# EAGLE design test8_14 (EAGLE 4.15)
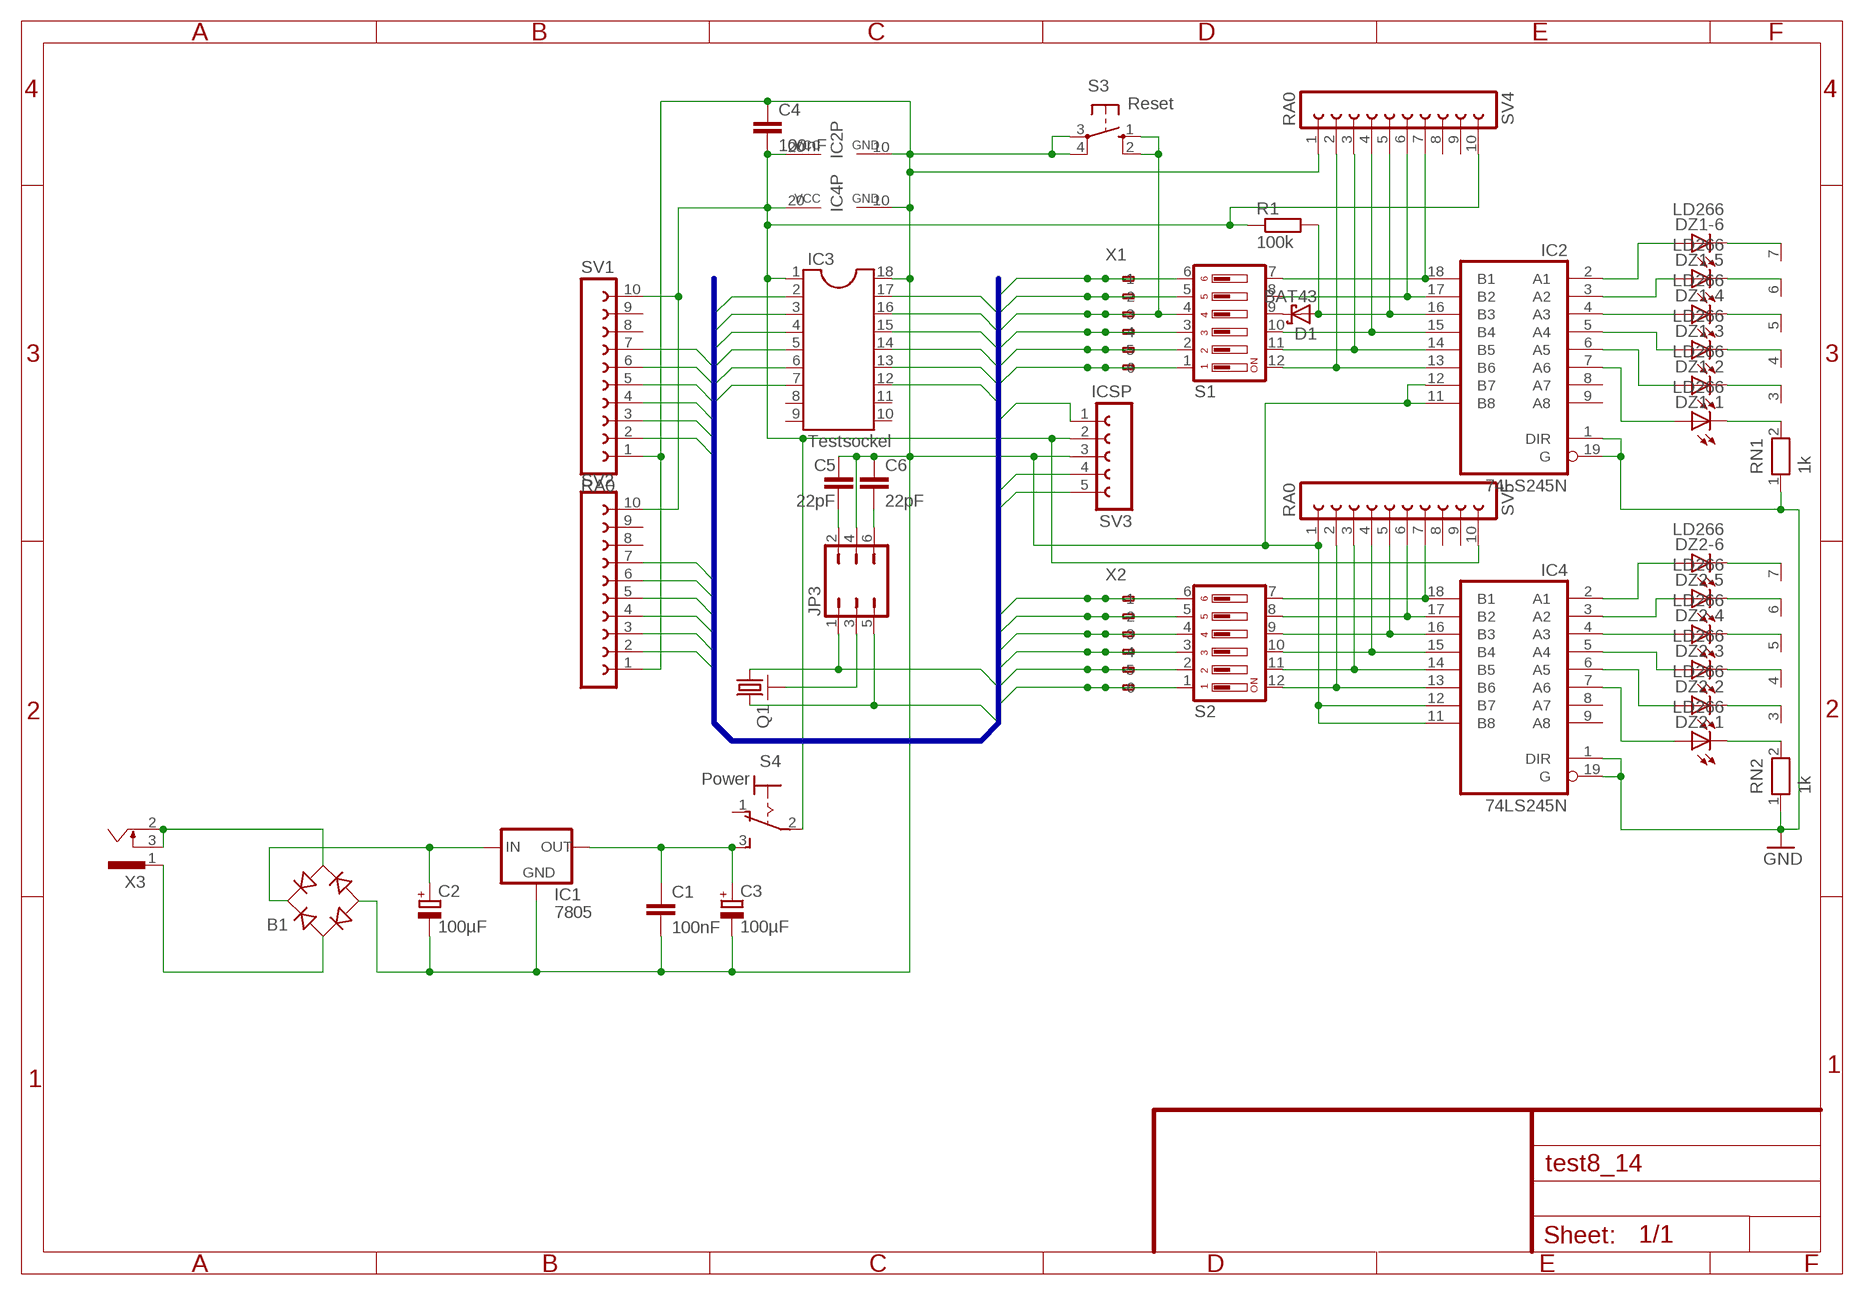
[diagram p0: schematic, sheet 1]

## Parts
B1  RB1A  [RB1A]
C1  100nF  C-EU050-025X075  [C050-025X075]
C2  100µF  CPOL-EUE2.5-7  [E2,5-7]
C3  100µF  CPOL-EUE2.5-7  [E2,5-7]
C4  100nF  C-EU050-025X075  [C050-025X075]
C5  22pF  C-EU025-025X050  [C025-025X050]
C6  22pF  C-EU025-025X050  [C025-025X050]
D1  BAT43  [DO35-10]
DZ1  LD266  [LD266]
DZ2  LD266  [LD266]
IC1  7805  78XXS  [78XXS]
IC2  74LS245N  [DIL20]
IC3  Testsockel  TEXTOOL18  [TEXTOOL18]
IC4  74LS245N  [DIL20]
JP3  JP3Q  [JP3Q]
Q1  RESONATOR  [RES3PIN]
R1  100k  R-EU_0207/12  [0207/12]
RN1  1k  RN06  [RN-7]
RN2  1k  RN06  [RN-7]
S1  DIP06YL  [DIP06YL]
S2  DIP06YL  [DIP06YL]
S3  Reset  10-XX  [B3F-10XX]
S4  Power  320-916  [320-916]
SV1  RA0  FE10-1  [FE10]
SV2  FE10-1  [FE10]
SV3  ICSP  FE05-1  [FE05-1]
SV4  RA0  FE10-1  [FE10]
SV5  RA0  FE10-1  [FE10]
X1  233-506  [233-506]
X2  233-506  [233-506]
X3  733989-55  [733989-5]

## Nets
GND: B1.- C1.2 C2.- C3.- C4.1 C5.1 C6.1 IC1.GND IC2.1(DIR) IC2.10(GND) IC2.11(B8) IC2.12(B7) IC2.19(G) IC3.18 IC4.1(DIR) IC4.10(GND) IC4.11(B8) IC4.12(B7) IC4.19(G) JP3.4 RN1.1 RN2.1 S3.3(P) S3.4(P1) SV1.1 SV2.1 SV3.3 SV4.1 SV5.1
N$1: DZ1.A2(-2:A) IC2.6(A5)
N$2: DZ1.A3(-3:A) IC2.5(A4)
N$3: DZ1.A4(-4:A) IC2.4(A3)
N$4: DZ1.A5(-5:A) IC2.3(A2)
N$5: DZ1.A1(-1:A) IC2.7(A6)
N$6: DZ1.A6(-6:A) IC2.2(A1)
N$7: DZ1.K6(-6:C) RN1.7
N$8: DZ1.K5(-5:C) RN1.6
N$9: DZ1.K4(-4:C) RN1.5
N$10: DZ1.K3(-3:C) RN1.4
N$11: DZ1.K2(-2:C) RN1.3
N$12: DZ1.K1(-1:C) RN1.2
N$13: DZ2.A4(-4:A) IC4.4(A3)
N$14: DZ2.A5(-5:A) IC4.3(A2)
N$15: DZ2.A6(-6:A) IC4.2(A1)
N$16: DZ2.A3(-3:A) IC4.5(A4)
N$17: DZ2.A2(-2:A) IC4.6(A5)
N$18: DZ2.A1(-1:A) IC4.7(A6)
N$19: DZ2.K6(-6:C) RN2.7
N$20: DZ2.K5(-5:C) RN2.6
N$21: DZ2.K4(-4:C) RN2.5
N$22: DZ2.K3(-3:C) RN2.4
N$23: DZ2.K2(-2:C) RN2.3
N$24: DZ2.K1(-1:C) RN2.2
N$25: IC2.18(B1) S1.7 SV4.7
N$26: IC2.17(B2) S1.8 SV4.6
N$27: D1.C S1.9
N$28: IC2.15(B4) S1.10 SV4.4
N$29: IC2.14(B5) S1.11 SV4.3
N$30: IC2.13(B6) S1.12 SV4.2
N$31: IC4.18(B1) S2.7 SV5.7
N$32: IC4.17(B2) S2.8 SV5.6
N$33: IC4.16(B3) S2.9 SV5.5
N$34: IC4.15(B4) S2.10 SV5.4
N$35: IC4.14(B5) S2.11 SV5.3
N$36: IC4.13(B6) S2.12 SV5.2
N$37: D1.A IC2.16(B3) R1.2 SV4.5
N$38: C5.2 JP3.2
N$39: C6.2 JP3.6
N$40: JP3.3 Q1.2
N$45: B1.+ C2.+ IC1.IN
N$48: B1.AC2 X3.2 X3.3
N$49: B1.AC1 X3.1
N$50: C1.1 C3.+ IC1.OUT S4.3(S)
RA0: IC3.17 S1.1 SV1.2 SV3.4 X1.A6(-6) X1.B6(B-6)
RA1: IC3.16 S1.2 SV1.3 SV3.5 X1.A5(-5) X1.B5(B-5)
RA2: IC3.15 S1.3 SV1.4 X1.A4(-4) X1.B4(B-4)
RA3: IC3.4 S1.4 S3.1(S) S3.2(S1) SV1.5 SV3.1 X1.A3(-3) X1.B3(B-3)
RA4: IC3.3 JP3.5 Q1.3 S1.5 SV1.6 X1.A2(-2) X1.B2(B-2)
RA5: IC3.2 JP3.1 Q1.1 S1.6 SV1.7 X1.A1(-1) X1.B1(B-1)
RC0: IC3.14 S2.1 SV2.2 X2.A6(-6) X2.B6(B-6)
RC1: IC3.13 S2.2 SV2.3 X2.A5(-5) X2.B5(B-5)
RC2: IC3.12 S2.3 SV2.4 X2.A4(-4) X2.B4(B-4)
RC3: IC3.7 S2.4 SV2.5 X2.A3(-3) X2.B3(B-3)
RC4: IC3.6 S2.5 SV2.6 X2.A2(-2) X2.B2(B-2)
RC5: IC3.5 S2.6 SV2.7 X2.A1(-1) X2.B1(B-1)
VSS: C4.2 IC2.20(VCC) IC3.1 IC4.20(VCC) R1.1 S4.2(P) SV1.10 SV2.10 SV3.2 SV4.10 SV5.10
Unconnected: IC2.8(A7) IC2.9(A8) IC3.8 IC3.9 IC3.10 IC3.11 IC4.8(A7) IC4.9(A8) S4.1(O) SV1.8 SV1.9 SV2.8 SV2.9 SV4.8 SV4.9 SV5.8 SV5.9

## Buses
RA[0..5],RC[0..5]

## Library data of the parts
B1 = rectifier:RB1A: RECTIFIER 1 A
C1 C4-C6 = rcl:C-EU: CAPACITOR, European symbol
C2 C3 = rcl:CPOL-EU: POLARIZED CAPACITOR, European symbol
D1 = sprut:BAT43: DIODE
DZ1 DZ2 = led:LD266: LED BLOCK 6 LEDs, Siemens
IC1 = v-reg:78XXS: VOLTAGE REGULATOR
IC2 IC4 = 74xx-eu:74*245: Octal BUS TRANSCEIVER, 3-state
IC3 = sprut:TEXTOOL18: Dual In Line
JP3 = jumper:JP3Q: JUMPER
Q1 = sprut:RESONATOR: CRYSTAL
R1 = rcl:R-EU_: RESISTOR, European symbol
RN1 RN2 = resistor-net:RN06: RESISTOR NETWORK
S1 S2 = switch-dil:DIP06YL: DIL/CODE SWITCH
S3 = switch-omron:10-XX: OMRON SWITCH
S4 = switch:320-916: TOGGLE SWITCH distributor RS Components
SV1 SV2 SV4 SV5 = con-lsta:FE10-1: FEMALE HEADER
SV3 = con-lsta:FE05-1: FEMALE HEADER
X1 X2 = con-wago:233-506: WAGO Cage Clamp
X3 = con-conrad:733989-55: FEMALE PRINT CONNECTOR 1.1 mm, FUK HING Industries, distributor Conrad

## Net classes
1 VCC: width 5.08 mm
2 GND: width 5.08 mm

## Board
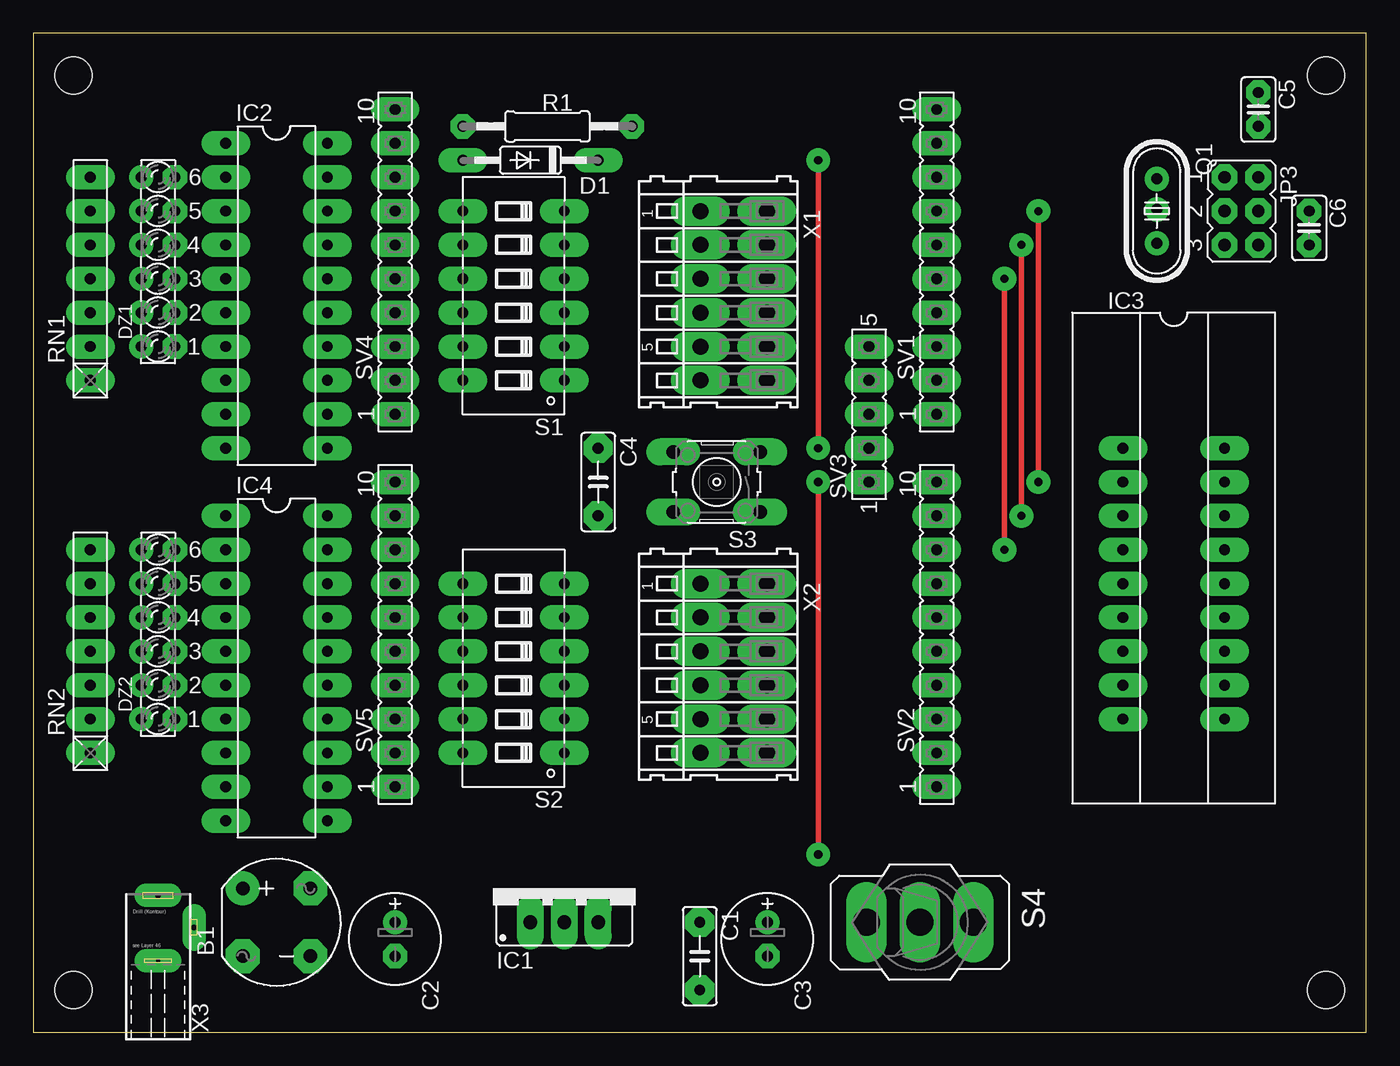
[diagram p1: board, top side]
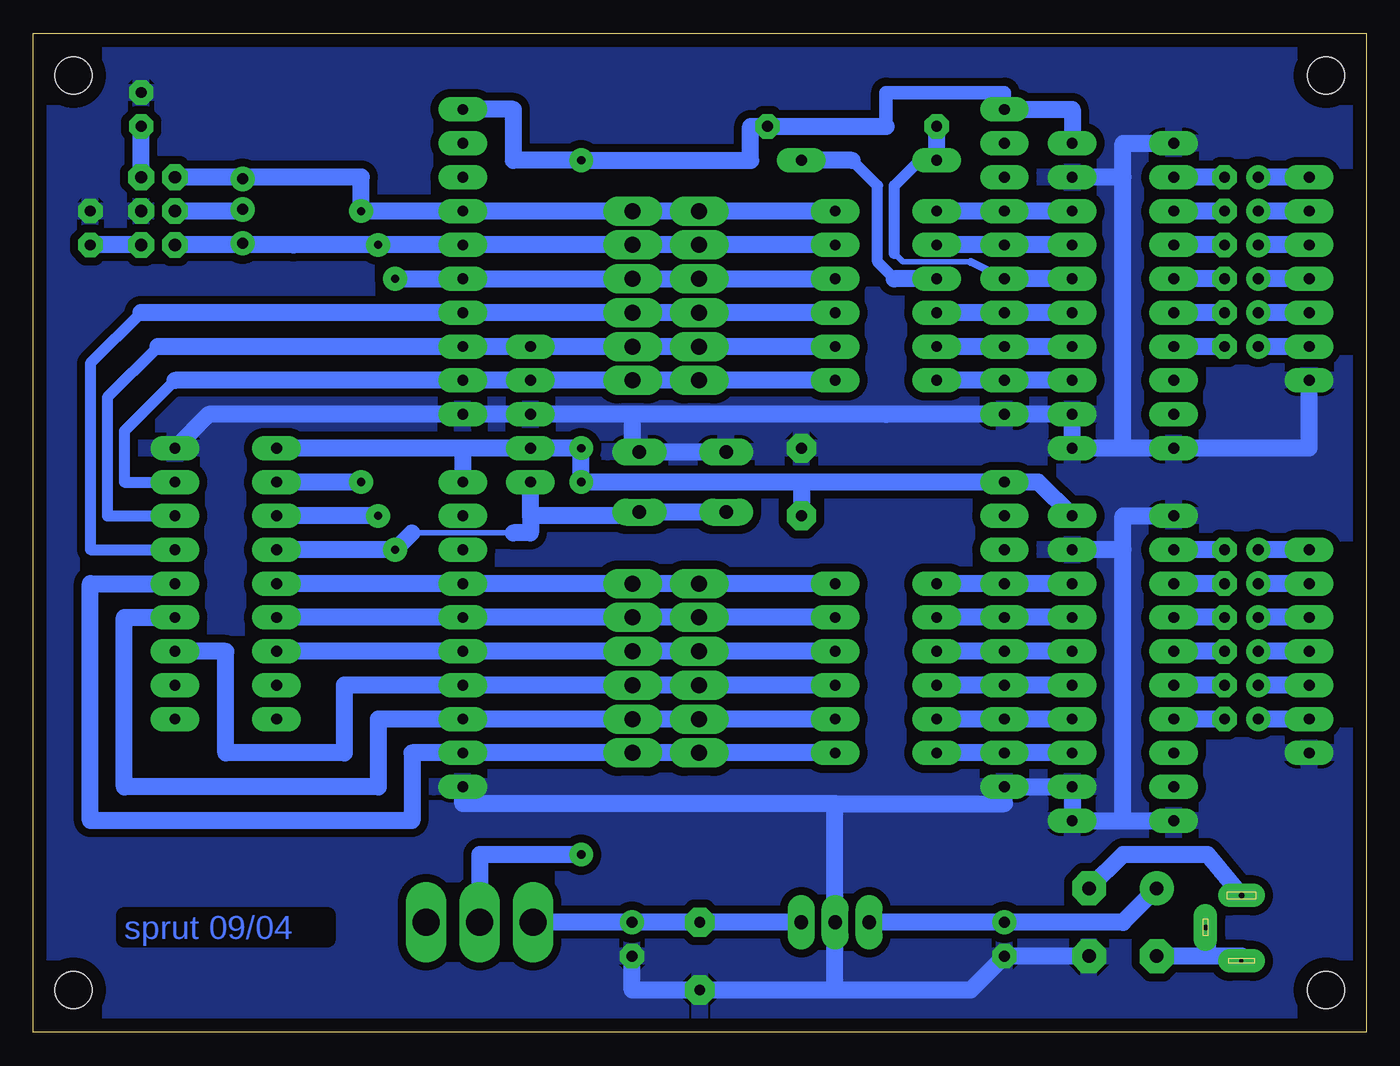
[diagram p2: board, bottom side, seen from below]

Size 100 x 74.92 mm. Coordinates in mm from the lower left corner, seen from the top.
Outline: 0,0 100,0 100,74.92 0,74.92 0,0
Copper layers (1*16): Top 0.035mm / dielectric 1.5mm / Bottom 0.035mm
Design rules "leiterplatte mit löchern": minimum track width 10mil, minimum drill 12mil, track to track 8mil, track to pad 8mil, pad to pad 8mil, via to via 8mil, smd to smd 8mil, copper to edge 40mil, drill to drill 8mil, minimum pad ring 20mil, minimum via ring 8mil, stop-mask expansion 4mil, vias tented up to drill 0mil, thermal gap 10mil
Holes 2.8 mm at 3.01,71.75 96.99,71.75 96.99,3.17 3.01,3.17

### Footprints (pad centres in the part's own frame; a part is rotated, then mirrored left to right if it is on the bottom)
RB1A = drill 1.016 pad 2.54 round: + -2.54,2.54 | drill 1.016 pad 2.54 octagon: - 2.54,-2.54; AC1 2.54,2.54; AC2 -2.54,-2.54
C050-025X075 = drill 0.813 pad 2.184 octagon: 1 -2.54,0; 2 2.54,0
E2,5-7 = drill 0.813 pad 1.6 round: + -1.27,0 | drill 0.813 pad 1.6 octagon: - 1.27,0
C025-025X050 = drill 0.813 pad 1.778 octagon: 1 -1.27,0; 2 1.27,0
DO35-10 = drill 0.813 long: A 5.08,0; C -5.08,0
LD266 = drill 0.813 octagon: A1 -1.27,6.35; A2 -1.27,3.81; A3 -1.27,1.27; A4 -1.27,-1.27; A5 -1.27,-3.81; A6 -1.27,-6.35 | drill 0.813 round: K1 1.27,6.35; K2 1.27,3.81; K3 1.27,1.27; K4 1.27,-1.27; K5 1.27,-3.81; K6 1.27,-6.35
78XXS = drill 1.016 long: GND 0,-2.54; IN -2.54,-2.54; OUT 2.54,-2.54
DIL20 = drill 0.813 long: 1 -11.43,-3.81; 2 -8.89,-3.81; 3 -6.35,-3.81; 4 -3.81,-3.81; 5 -1.27,-3.81; 6 1.27,-3.81; 7 3.81,-3.81; 8 6.35,-3.81; 9 8.89,-3.81; 10 11.43,-3.81; 11 11.43,3.81; 12 8.89,3.81; 13 6.35,3.81; 14 3.81,3.81; 15 1.27,3.81; 16 -1.27,3.81; 17 -3.81,3.81; 18 -6.35,3.81; 19 -8.89,3.81; 20 -11.43,3.81
TEXTOOL18 = drill 0.813 long: 1 -10.16,-3.81; 2 -7.62,-3.81; 3 -5.08,-3.81; 4 -2.54,-3.81; 5 0,-3.81; 6 2.54,-3.81; 7 5.08,-3.81; 8 7.62,-3.81; 9 10.16,-3.81; 10 10.16,3.81; 11 7.62,3.81; 12 5.08,3.81; 13 2.54,3.81; 14 0,3.81; 15 -2.54,3.81; 16 -5.08,3.81; 17 -7.62,3.81; 18 -10.16,3.81
JP3Q = drill 0.914 octagon: 1 -2.54,-1.27; 2 -2.54,1.27; 3 0,-1.27; 4 0,1.27; 5 2.54,-1.27; 6 2.54,1.27
RES3PIN = drill 0.813 round: 1 -2.413,0; 2 -0.127,0; 3 2.413,0
0207/12 = drill 0.813 octagon: 1 -6.35,0; 2 6.35,0
RN-7 = drill 0.813 long: 1 -7.62,0; 2 -5.08,0; 3 -2.54,0; 4 0,0; 5 2.54,0; 6 5.08,0; 7 7.62,0
DIP06YL = drill 0.813 long: 1 -6.35,-3.81; 2 -3.81,-3.81; 3 -1.27,-3.81; 4 1.27,-3.81; 5 3.81,-3.81; 6 6.35,-3.81; 7 6.35,3.81; 8 3.81,3.81; 9 1.27,3.81; 10 -1.27,3.81; 11 -3.81,3.81; 12 -6.35,3.81
B3F-10XX = drill 1.016 long: 1 -3.251,2.261; 2 3.251,2.261; 3 -3.251,-2.261; 4 3.251,-2.261
320-916 = drill 2.007 long: 1 0,4.013; 2 0,0; 3 0,-4.013
FE10 = drill 0.813 long: 1 -11.43,0; 2 -8.89,0; 3 -6.35,0; 4 -3.81,0; 5 -1.27,0; 6 1.27,0; 7 3.81,0; 8 6.35,0; 9 8.89,0; 10 11.43,0
FE05-1 = drill 0.813 long: 1 -5.08,0; 2 -2.54,0; 3 0,0; 4 2.54,0; 5 5.08,0
233-506 = drill 1.2 long: A1 -6.35,2.5; A2 -3.81,2.5; A3 -1.27,2.5; A4 1.27,2.5; A5 3.81,2.5; A6 6.35,2.5; B1 -6.35,-2.5; B2 -3.81,-2.5; B3 -1.27,-2.5; B4 1.27,-2.5; B5 3.81,-2.5; B6 6.35,-2.5
733989-5 = drill 0.4 pad 1.778 long: 1 0,5.82; 3 2.7,3.42 | drill 0.3 pad 1.778 long: 2 0,0.92

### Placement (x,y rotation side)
B1  18.25,8.25 0 top
C1  50,5.71 270 top
C2  27.14,6.98 270 top
C3  55.08,6.98 270 top
C4  42.38,41.27 270 top
C5  91.91,69.21 270 top
C6  95.72,60.32 270 top
D1  37.3,65.4 180 top
DZ1  9.36,57.78 180 top
DZ2  9.36,29.84 180 top
IC1  39.84,10.79 0 top
IC2  18.25,55.24 270 top
IC3  85.56,33.65 270 top
IC4  18.25,27.3 270 top
JP3  90.64,61.59 270 top
Q1  84.29,61.59 270 top
R1  38.57,67.94 180 top
RN1  4.28,56.51 90 top
RN2  4.28,28.57 90 top
S1  36.03,55.24 90 top
S2  36.03,27.3 90 top
S3  51.27,41.27 180 top
S4  66.51,8.25 270 top
SV1  67.78,57.78 90 top
SV2  67.78,29.84 90 top
SV3  62.7,46.35 90 top
SV4  27.14,57.78 90 top
SV5  27.14,29.84 90 top
X1  52.54,55.24 270 top
X2  52.54,27.3 270 top
X3  9.36,4.44 0 top

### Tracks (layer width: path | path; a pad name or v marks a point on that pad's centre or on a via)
GND
  Bottom 1.27: RN1.1 4.28,43.81 IC2.10 18.25,43.81 | 18.25,43.81 18.25,64.13 | 18.25,64.13 IC2.19 | 18.25,15.87 18.25,36.19 | 18.25,36.19 IC4.19 | B1.- C2.- 29.68,3.17 39.84,3.17 | 39.84,3.17 C1.2 55.08,3.17 C3.- | 39.84,3.17 IC1.GND 39.84,17.14 | S3.3 S3.4 | S3.3 S3.4 | S3.4 47.74,43.53 47.46,43.81 | S3.3 S3.4 | S3.3 54.8,43.53 55.08,43.81 55.08,46.35 | SV2.1 67.78,17.14 39.84,17.14 | 39.84,17.14 27.14,17.14 SV5.1 IC4.12 IC4.11 18.25,15.87 | IC2.11 IC2.12 | 18.25,43.81 IC2.11 | IC2.12 SV4.1 36.03,46.35 | 18.25,15.87 IC4.10 | 36.03,46.35 55.08,46.35 | 55.08,46.35 SV3.3 SV1.1 86.83,46.35 IC3.18 | IC2.11 IC2.12 | IC2.12 36.03,46.35 | IC2.1 18.25,66.67 18.25,64.13 | IC4.1 18.25,38.73 18.25,36.19
  pour Bottom (isolate 0.61): -2.07,-1.91 100.8,-1.91 100.8,76.83 -2.07,76.83
N$1
  Bottom 1.27: DZ1.A2 IC2.6
N$2
  Bottom 1.27: DZ1.A3 IC2.5
N$3
  Bottom 1.27: DZ1.A4 IC2.4
N$4
  Bottom 1.27: DZ1.A5 IC2.3
N$5
  Bottom 1.27: DZ1.A1 IC2.7
N$6
  Bottom 1.27: DZ1.A6 IC2.2
N$7
  Bottom 1.27: RN1.7 DZ1.K6
N$8
  Bottom 1.27: RN1.6 DZ1.K5
N$9
  Bottom 1.27: RN1.5 DZ1.K4
N$10
  Bottom 1.27: RN1.4 DZ1.K3
N$11
  Bottom 1.27: RN1.3 DZ1.K2
N$12
  Bottom 1.27: RN1.2 DZ1.K1
N$13
  Bottom 1.27: DZ2.A4 IC4.4
N$14
  Bottom 1.27: DZ2.A5 IC4.3
N$15
  Bottom 1.27: DZ2.A6 IC4.2
N$16
  Bottom 1.27: DZ2.A3 IC4.5
N$17
  Bottom 1.27: DZ2.A2 IC4.6
N$18
  Bottom 1.27: DZ2.A1 IC4.7
N$19
  Bottom 1.27: RN2.7 DZ2.K6
N$20
  Bottom 1.27: RN2.6 DZ2.K5
N$21
  Bottom 1.27: RN2.5 DZ2.K4
N$22
  Bottom 1.27: RN2.4 DZ2.K3
N$23
  Bottom 1.27: RN2.3 DZ2.K2
N$24
  Bottom 1.27: RN2.2 DZ2.K1
N$25
  Bottom 0.406: SV4.7 S1.7
  Bottom 1.27: IC2.18 SV4.7 S1.7
N$26
  Bottom 0.406: SV4.6 S1.8
  Bottom 1.27: IC2.17 SV4.6 S1.8
N$27
  Bottom 0.813: 35.39,56.51 36.66,57.78 36.66,63.5 38.57,65.4
  Bottom 1.27: S1.9 35.39,56.51 | 38.57,65.4 D1.C
N$28
  Bottom 0.406: SV4.4 S1.10
  Bottom 1.27: IC2.15 SV4.4 S1.10
N$29
  Bottom 0.406: SV4.3 S1.11
  Bottom 1.27: IC2.14 SV4.3 S1.11
N$30
  Bottom 0.406: SV4.2 S1.12
  Bottom 1.27: IC2.13 SV4.2 S1.12
N$31
  Bottom 0.406: SV5.7 S2.7
  Bottom 1.27: IC4.18 SV5.7 S2.7
N$32
  Bottom 0.406: SV5.6 S2.8
  Bottom 1.27: IC4.17 SV5.6 S2.8
N$33
  Bottom 0.406: SV5.5 S2.9
  Bottom 1.27: IC4.16 SV5.5 S2.9
N$34
  Bottom 0.406: SV5.4 S2.10
  Bottom 1.27: IC4.15 SV5.4 S2.10
N$35
  Bottom 0.406: SV5.3 S2.11
  Bottom 1.27: IC4.14 SV5.3 S2.11
N$36
  Bottom 0.406: SV5.2 S2.12
  Bottom 1.27: IC4.13 SV5.2 S2.12
N$37
  Bottom 0.406: 29.68,57.78 34.76,57.78 35.39,58.42
  Bottom 0.61: SV4.5 29.68,57.78
  Bottom 0.813: 35.39,58.42 35.39,63.5 33.49,65.4 D1.A
  Bottom 1.27: D1.A R1.2 | IC2.16 SV4.5
N$38
  Bottom 1.27: JP3.2 C5.2
N$39
  Bottom 1.27: JP3.6 C6.2
N$40
  Bottom 0.406: Q1.2 84.29,61.59
  Bottom 1.27: 84.29,61.59 JP3.3
N$45
  Bottom 1.27: B1.+ 18.25,8.25 C2.+ IC1.IN
N$48
  Bottom 0.406: 11.9,8.25 11.9,7.86 X3.3
  Bottom 0.813: X3.2 9.36,5.71
  Bottom 1.27: 11.9,5.71 B1.AC2 | 11.9,5.71 11.9,7.86 | 9.36,5.71 11.9,5.71
N$49
  Bottom 1.27: X3.1 11.9,13.33 18.25,13.33 B1.AC1
N$50
  Bottom 1.27: IC1.OUT C1.1 C3.+ S4.3
RA0
  Bottom 0.406: X1.A6 55.08,48.89 | SV3.4 SV1.2
  Bottom 0.813: IC3.17 93.18,41.27 93.18,45.08 89.37,48.89
  Bottom 1.27: S1.1 X1.B6 X1.A6 SV3.4 SV1.2 89.37,48.89
RA1
  Bottom 0.406: X1.A5 55.08,51.43 | SV3.5 SV1.3
  Bottom 0.813: IC3.16 94.45,38.73 94.45,47.62 90.64,51.43
  Bottom 1.27: S1.2 X1.B5 X1.A5 SV3.5 SV1.3 90.64,51.43
RA2
  Bottom 0.406: 55.08,53.97 X1.A4
  Bottom 0.813: IC3.15 95.72,36.19 95.72,50.16 91.91,53.97
  Bottom 1.27: S1.3 X1.B4 55.08,53.97 SV1.4 91.91,53.97
RA3  (via drill 0.61 pad 1.78)
  Top 0.406: v72.86,36.19 v72.86,56.51
  Bottom 0.406: 55.08,56.51 X1.A3 | 63.97,37.46 71.59,37.46
  Bottom 1.27: S1.4 X1.B3 55.08,56.51 SV1.5 v72.86,56.51 | IC3.4 v72.86,36.19 71.59,37.46 | 62.7,38.73 62.7,37.46 63.97,37.46 | 62.7,38.73 SV3.1 | S3.2 S3.1 54.8,39.01 55.08,38.73 62.7,38.73
RA4  (via drill 0.61 pad 1.78)
  Top 0.406: v74.13,59.05 v74.13,38.73
  Bottom 0.406: X1.B2 51.27,59.05 | 55.08,59.05 X1.A2 | 84.29,59.05 Q1.3
  Bottom 1.27: S1.5 X1.B2 55.08,59.05 SV1.6 v74.13,59.05 80.48,59.05 84.29,59.05 JP3.5 | v74.13,38.73 IC3.3
RA5  (via drill 0.61 pad 1.78)
  Top 0.406: v75.4,61.59 v75.4,41.27
  Bottom 0.406: 55.08,61.59 X1.A1 | 84.29,64.13 Q1.1
  Bottom 1.27: S1.6 X1.B1 55.08,61.59 SV1.7 v75.4,61.59 75.4,64.13 80.48,64.13 84.29,64.13 JP3.1 | v75.4,41.27 IC3.2
RC0
  Bottom 0.406: X2.A6 55.08,20.95
  Bottom 1.27: S2.1 X2.B6 X2.A6 SV2.2 71.59,20.95 71.59,15.87 95.72,15.87 95.72,33.65 IC3.14
RC1
  Bottom 0.406: X2.A5 55.08,23.49
  Bottom 1.27: S2.2 X2.B5 X2.A5 SV2.3 74.13,23.49 74.13,18.41 93.18,18.41 93.18,31.11 IC3.13
RC2
  Bottom 0.406: X2.A4 55.08,26.03
  Bottom 1.27: S2.3 X2.B4 X2.A4 SV2.4 76.67,26.03 76.67,20.95 85.56,20.95 85.56,28.57 IC3.12
RC3
  Bottom 0.406: X2.A3 55.08,28.57
  Bottom 1.27: S2.4 X2.B3 X2.A3 SV2.5 IC3.7
RC4
  Bottom 0.406: 55.08,31.11 X2.A2
  Bottom 1.27: S2.5 X2.B2 55.08,31.11 SV2.6 IC3.6
RC5
  Bottom 0.406: 55.08,33.65 X2.A1
  Bottom 1.27: S2.6 X2.B1 55.08,33.65 SV2.7 IC3.5
VSS  (via drill 0.61 pad 1.78)
  Top 0.406: v58.89,41.27 v58.89,13.33 | v58.89,43.81 v58.89,65.4
  Bottom 1.016: SV4.10 27.14,70.48 36.03,70.48 36.03,67.94
  Bottom 1.27: IC2.20 22.06,69.21 SV4.10 | 36.03,67.94 R1.1 46.19,67.94 46.19,65.4 v58.89,65.4 63.97,65.4 63.97,69.21 SV1.10 | 67.78,43.81 SV3.2 v58.89,43.81 v58.89,41.27 42.38,41.27 | 67.78,43.81 SV2.10 | 67.78,43.81 IC3.1 | S4.2 66.51,13.33 v58.89,13.33 | IC4.20 24.6,41.27 | 24.6,41.27 SV5.10 | 24.6,41.27 42.38,41.27 | 42.38,41.27 C4.2

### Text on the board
Bottom: sprut 09/04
